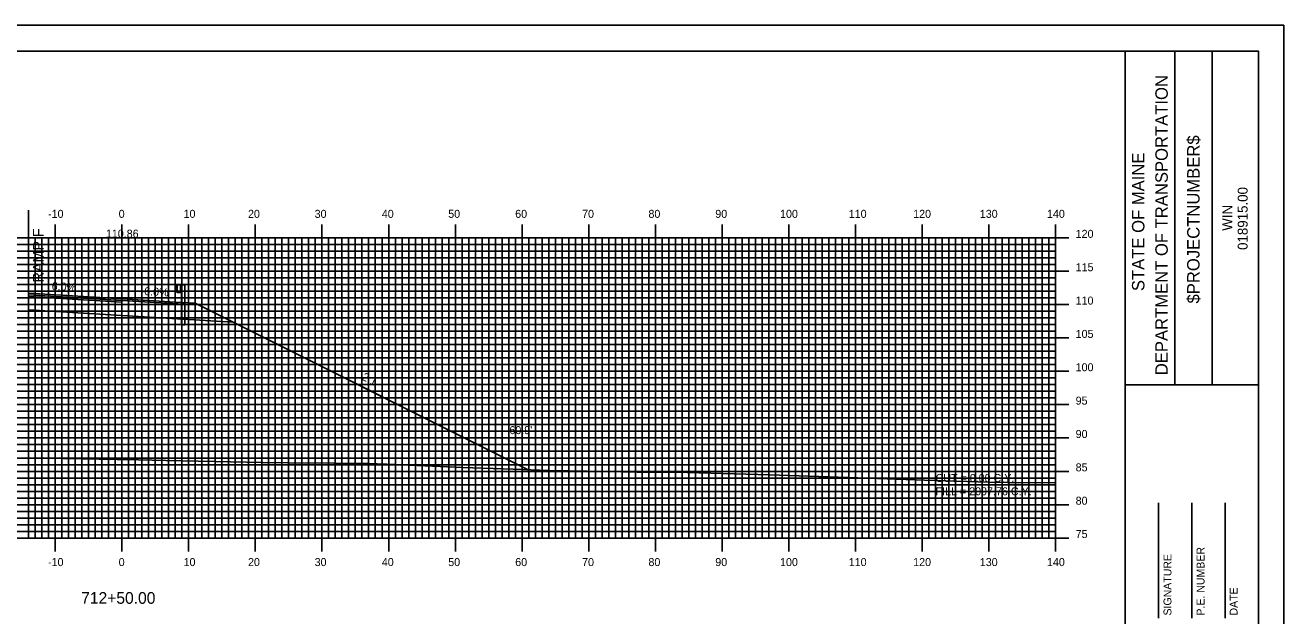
# Model space of a CAD drawing. Extents: x 855297 to 855640, y 364366 to 364586.
# Drawn here: x 855448.3 to 855637, y 364497.1 to 364585.7 of the extents above; entities that cross this region are included whole.
import ezdxf

# ---------------------------------------------------------------- set-up
doc = ezdxf.new("R2010")
doc.units = 0
for name, color, linetype in [('ANNOTATION', 7, 'Continuous'), ('BORDER', 7, 'Continuous'), ('D_Guardrail_Beam_Rt', 7, 'Continuous'), ('D_Roadway_Centerline', 7, 'Continuous'), ('D_Roadway_Centerline_Text', 7, 'Continuous'), ('D_Roadway_Edge_Shoulder', 7, 'Continuous'), ('D_Roadway_Edge_TW', 7, 'Continuous'), ('D_Roadway_Pavement', 7, 'Continuous'), ('D_Roadway_SlopeLines', 7, 'Continuous'), ('D_Roadway_SubGrade', 7, 'Continuous'), ('D_Text_Standard', 7, 'Continuous'), ('H_V ANNOTATION', 7, 'Continuous'), ('MAJOR', 7, 'Continuous'), ('MINOR', 7, 'Continuous'), ('PLOT BOUNDARY', 7, 'Continuous'), ('S_Roadway_Centerline', 7, 'Continuous')]:
    doc.layers.add(name, color=color, linetype=linetype)

msp = doc.modelspace()

# ---------------------------------------------------------------- linework, layer by layer
at = {"layer": 'BORDER'}
for p, q in [((855613.17, 364371.79), (855613.17, 364581.79)), ((855620.63, 364531.78), (855620.63, 364581.78)), ((855626.22, 364531.78), (855626.22, 364581.78)), ((855613.17, 364531.78), (855633.17, 364531.78)), ((855618.17, 364496.79), (855618.17, 364514.09)), ((855623.17, 364496.79), (855623.17, 364514.09)), ((855628.17, 364496.79), (855628.17, 364514.09))]:
    msp.add_line(p, q, dxfattribs=at)
msp.add_lwpolyline([(855313.17, 364371.79), (855633.17, 364371.79), (855633.17, 364581.79), (855313.17, 364581.79)], close=True, dxfattribs=at)
at = {"layer": 'D_Guardrail_Beam_Rt'}
for p, q in [((855470.95, 364546.64), (855470.81, 364546.54)), ((855470.81, 364546.4), (855471, 364546.26)), ((855471, 364546.06), (855470.81, 364545.93)), ((855470.81, 364545.79), (855470.95, 364545.69)), ((855471.04, 364546.66), (855470.97, 364546.65)), ((855470.97, 364545.68), (855471.04, 364545.66)), ((855471.04, 364546.75), (855471.73, 364546.75)), ((855471.04, 364545.58), (855471.04, 364546.75)), ((855471.04, 364546.2), (855471.04, 364546.13)), ((855471.73, 364545.58), (855471.04, 364545.58)), ((855471.56, 364546.75), (855471.56, 364545.58)), ((855471.67, 364546.75), (855471.67, 364545.58)), ((855471.71, 364540.75), (855471.71, 364545.58)), ((855471.73, 364546.75), (855472.2, 364546.75)), ((855471.73, 364546.75), (855471.73, 364545.58)), ((855472.2, 364546.75), (855472.2, 364540.75)), ((855471.71, 364540.75), (855472.2, 364540.75))]:
    msp.add_line(p, q, dxfattribs=at)
for centre, major_axis, start_param, end_param in [((855470.86, 364546.47), (-0.0877, 0), 5.323254, 7.243116), ((855470.86, 364545.86), (-0.0877, 0), 5.323254, 7.243116), ((855470.97, 364546.61), (-0.0417, 0), 4.907132, 5.323254), ((855470.97, 364545.72), (-0.0417, 0), 0.959931, 1.376053), ((855470.96, 364546.2), (0.0789, 0), 0, 0.959931), ((855470.96, 364546.13), (0.0789, 0), 5.323254, 6.283185)]:
    msp.add_ellipse(centre, major_axis=major_axis, ratio=0.995501, start_param=start_param, end_param=end_param, dxfattribs=at)
at = {"layer": 'D_Roadway_Centerline'}
msp.add_lwpolyline([(855448.77, 364545.48), (855462.77, 364544.64), (855470.77, 364544.16), (855473.77, 364543.98), (855479.45, 364541.14), (855523.67, 364519.03)], dxfattribs=at)
at = {"layer": 'D_Roadway_Edge_Shoulder'}
msp.add_lwpolyline([(855462.77, 364544.64), (855470.77, 364544.16), (855470.77, 364544.16), (855473.77, 364543.98), (855473.77, 364543.73), (855462.77, 364544.39)], close=True, dxfattribs=at)
at = {"layer": 'D_Roadway_Edge_TW'}
msp.add_lwpolyline([(855448.77, 364545.48), (855462.77, 364544.64), (855462.77, 364544.39), (855448.77, 364545.23)], close=True, dxfattribs=at)
at = {"layer": 'D_Roadway_Pavement'}
msp.add_lwpolyline([(855448.77, 364545.23), (855462.77, 364544.39), (855462.77, 364544.14), (855448.77, 364544.98)], close=True, dxfattribs=at)
msp.add_lwpolyline([(855462.77, 364544.39), (855462.77, 364544.14)], dxfattribs=at)
msp.add_lwpolyline([(855462.77, 364544.39), (855462.77, 364544.14)], dxfattribs=at)
at = {"layer": 'D_Roadway_SlopeLines'}
msp.add_lwpolyline([(855473.77, 364543.98), (855523.67, 364519.03)], dxfattribs=at)
at = {"layer": 'D_Roadway_SubGrade'}
msp.add_line((855448.77, 364557.94), (855448.77, 364542.98), dxfattribs=at)
for points in [[(855448.77, 364544.98), (855462.77, 364544.14), (855462.77, 364542.14), (855448.77, 364542.98)], [(855462.77, 364544.14), (855462.77, 364544.39), (855473.77, 364543.73), (855473.77, 364543.98), (855479.45, 364541.14), (855462.77, 364542.14)]]:
    msp.add_lwpolyline(points, close=True, dxfattribs=at)
at = {"layer": 'MAJOR'}
for p, q in [((855452.77, 364555.79), (855452.77, 364553.79)), ((855462.77, 364555.79), (855462.77, 364553.79)), ((855472.77, 364555.79), (855472.77, 364553.79)), ((855482.77, 364555.79), (855482.77, 364553.79)), ((855492.77, 364555.79), (855492.77, 364553.79)), ((855502.77, 364555.79), (855502.77, 364553.79)), ((855512.77, 364555.79), (855512.77, 364553.79)), ((855522.77, 364555.79), (855522.77, 364553.79)), ((855532.77, 364555.79), (855532.77, 364553.79)), ((855542.77, 364555.79), (855542.77, 364553.79)), ((855552.77, 364555.79), (855552.77, 364553.79)), ((855562.77, 364555.79), (855562.77, 364553.79)), ((855572.77, 364555.79), (855572.77, 364553.79)), ((855582.77, 364555.79), (855582.77, 364553.79)), ((855592.77, 364555.79), (855592.77, 364553.79)), ((855602.77, 364555.79), (855602.77, 364553.79)), ((855322.77, 364553.79), (855602.77, 364553.79)), ((855322.77, 364553.79), (855602.77, 364553.79)), ((855452.77, 364508.79), (855452.77, 364553.79)), ((855462.77, 364508.79), (855462.77, 364553.79)), ((855472.77, 364508.79), (855472.77, 364553.79)), ((855482.77, 364508.79), (855482.77, 364553.79)), ((855492.77, 364508.79), (855492.77, 364553.79)), ((855502.77, 364508.79), (855502.77, 364553.79)), ((855512.77, 364508.79), (855512.77, 364553.79)), ((855522.77, 364508.79), (855522.77, 364553.79)), ((855532.77, 364508.79), (855532.77, 364553.79)), ((855542.77, 364508.79), (855542.77, 364553.79)), ((855552.77, 364508.79), (855552.77, 364553.79)), ((855562.77, 364508.79), (855562.77, 364553.79)), ((855572.77, 364508.79), (855572.77, 364553.79)), ((855582.77, 364508.79), (855582.77, 364553.79)), ((855592.77, 364508.79), (855592.77, 364553.79)), ((855604.77, 364553.79), (855600.77, 364553.79)), ((855602.77, 364508.79), (855602.77, 364553.79)), ((855602.77, 364508.79), (855602.77, 364553.79)), ((855322.77, 364548.79), (855602.77, 364548.79)), ((855604.77, 364548.79), (855600.77, 364548.79)), ((855322.77, 364543.79), (855602.77, 364543.79)), ((855604.77, 364543.79), (855600.77, 364543.79)), ((855322.77, 364538.79), (855602.77, 364538.79)), ((855604.77, 364538.79), (855600.77, 364538.79)), ((855322.77, 364533.79), (855602.77, 364533.79)), ((855604.77, 364533.79), (855600.77, 364533.79)), ((855322.77, 364528.79), (855602.77, 364528.79)), ((855604.77, 364528.79), (855600.77, 364528.79)), ((855322.77, 364523.79), (855602.77, 364523.79)), ((855604.77, 364523.79), (855600.77, 364523.79)), ((855322.77, 364518.79), (855602.77, 364518.79)), ((855604.77, 364518.79), (855600.77, 364518.79)), ((855322.77, 364513.79), (855602.77, 364513.79)), ((855604.77, 364513.79), (855600.77, 364513.79)), ((855322.77, 364508.79), (855602.77, 364508.79)), ((855322.77, 364508.79), (855602.77, 364508.79)), ((855452.77, 364506.78), (855452.77, 364508.79)), ((855462.77, 364506.78), (855462.77, 364508.79)), ((855472.77, 364506.78), (855472.77, 364508.79)), ((855482.77, 364506.78), (855482.77, 364508.79)), ((855492.77, 364506.78), (855492.77, 364508.79)), ((855502.77, 364506.78), (855502.77, 364508.79)), ((855512.77, 364506.78), (855512.77, 364508.79)), ((855522.77, 364506.78), (855522.77, 364508.79)), ((855532.77, 364506.78), (855532.77, 364508.79)), ((855542.77, 364506.78), (855542.77, 364508.79)), ((855552.77, 364506.78), (855552.77, 364508.79)), ((855562.77, 364506.78), (855562.77, 364508.79)), ((855572.77, 364506.78), (855572.77, 364508.79)), ((855582.77, 364506.78), (855582.77, 364508.79)), ((855592.77, 364506.78), (855592.77, 364508.79)), ((855604.77, 364508.79), (855600.77, 364508.79)), ((855602.77, 364506.78), (855602.77, 364508.79))]:
    msp.add_line(p, q, dxfattribs=at)
at = {"layer": 'MINOR'}
for p, q in [((855322.77, 364552.79), (855602.77, 364552.79)), ((855448.77, 364508.79), (855448.77, 364553.79)), ((855449.77, 364508.79), (855449.77, 364553.79)), ((855450.77, 364508.79), (855450.77, 364553.79)), ((855451.77, 364508.79), (855451.77, 364553.79)), ((855453.77, 364508.79), (855453.77, 364553.79)), ((855454.77, 364508.79), (855454.77, 364553.79)), ((855455.77, 364508.79), (855455.77, 364553.79)), ((855456.77, 364508.79), (855456.77, 364553.79)), ((855457.77, 364508.79), (855457.77, 364553.79)), ((855458.77, 364508.79), (855458.77, 364553.79)), ((855459.77, 364508.79), (855459.77, 364553.79)), ((855460.77, 364508.79), (855460.77, 364553.79)), ((855461.77, 364508.79), (855461.77, 364553.79)), ((855463.77, 364508.79), (855463.77, 364553.79)), ((855464.77, 364508.79), (855464.77, 364553.79)), ((855465.77, 364508.79), (855465.77, 364553.79)), ((855466.77, 364508.79), (855466.77, 364553.79)), ((855467.77, 364508.79), (855467.77, 364553.79)), ((855468.77, 364508.79), (855468.77, 364553.79)), ((855469.77, 364508.79), (855469.77, 364553.79)), ((855470.77, 364508.79), (855470.77, 364553.79)), ((855471.77, 364508.79), (855471.77, 364553.79)), ((855473.77, 364508.79), (855473.77, 364553.79)), ((855474.77, 364508.79), (855474.77, 364553.79)), ((855475.77, 364508.79), (855475.77, 364553.79)), ((855476.77, 364508.79), (855476.77, 364553.79)), ((855477.77, 364508.79), (855477.77, 364553.79)), ((855478.77, 364508.79), (855478.77, 364553.79)), ((855479.77, 364508.79), (855479.77, 364553.79)), ((855480.77, 364508.79), (855480.77, 364553.79)), ((855481.77, 364508.79), (855481.77, 364553.79)), ((855483.77, 364508.79), (855483.77, 364553.79)), ((855484.77, 364508.79), (855484.77, 364553.79)), ((855485.77, 364508.79), (855485.77, 364553.79)), ((855486.77, 364508.79), (855486.77, 364553.79)), ((855487.77, 364508.79), (855487.77, 364553.79)), ((855488.77, 364508.79), (855488.77, 364553.79)), ((855489.77, 364508.79), (855489.77, 364553.79)), ((855490.77, 364508.79), (855490.77, 364553.79)), ((855491.77, 364508.79), (855491.77, 364553.79)), ((855493.77, 364508.79), (855493.77, 364553.79)), ((855494.77, 364508.79), (855494.77, 364553.79)), ((855495.77, 364508.79), (855495.77, 364553.79)), ((855496.77, 364508.79), (855496.77, 364553.79)), ((855497.77, 364508.79), (855497.77, 364553.79)), ((855498.77, 364508.79), (855498.77, 364553.79)), ((855499.77, 364508.79), (855499.77, 364553.79)), ((855500.77, 364508.79), (855500.77, 364553.79)), ((855501.77, 364508.79), (855501.77, 364553.79)), ((855503.77, 364508.79), (855503.77, 364553.79)), ((855504.77, 364508.79), (855504.77, 364553.79)), ((855505.77, 364508.79), (855505.77, 364553.79)), ((855506.77, 364508.79), (855506.77, 364553.79)), ((855507.77, 364508.79), (855507.77, 364553.79)), ((855508.77, 364508.79), (855508.77, 364553.79)), ((855509.77, 364508.79), (855509.77, 364553.79)), ((855510.77, 364508.79), (855510.77, 364553.79)), ((855511.77, 364508.79), (855511.77, 364553.79)), ((855513.77, 364508.79), (855513.77, 364553.79)), ((855514.77, 364508.79), (855514.77, 364553.79)), ((855515.77, 364508.79), (855515.77, 364553.79)), ((855516.77, 364508.79), (855516.77, 364553.79)), ((855517.77, 364508.79), (855517.77, 364553.79)), ((855518.77, 364508.79), (855518.77, 364553.79)), ((855519.77, 364508.79), (855519.77, 364553.79)), ((855520.77, 364508.79), (855520.77, 364553.79)), ((855521.77, 364508.79), (855521.77, 364553.79)), ((855523.77, 364508.79), (855523.77, 364553.79)), ((855524.77, 364508.79), (855524.77, 364553.79)), ((855525.77, 364508.79), (855525.77, 364553.79)), ((855526.77, 364508.79), (855526.77, 364553.79)), ((855527.77, 364508.79), (855527.77, 364553.79)), ((855528.77, 364508.79), (855528.77, 364553.79)), ((855529.77, 364508.79), (855529.77, 364553.79)), ((855530.77, 364508.79), (855530.77, 364553.79)), ((855531.77, 364508.79), (855531.77, 364553.79)), ((855533.77, 364508.79), (855533.77, 364553.79)), ((855534.77, 364508.79), (855534.77, 364553.79)), ((855535.77, 364508.79), (855535.77, 364553.79)), ((855536.77, 364508.79), (855536.77, 364553.79)), ((855537.77, 364508.79), (855537.77, 364553.79)), ((855538.77, 364508.79), (855538.77, 364553.79)), ((855539.77, 364508.79), (855539.77, 364553.79)), ((855540.77, 364508.79), (855540.77, 364553.79)), ((855541.77, 364508.79), (855541.77, 364553.79)), ((855543.77, 364508.79), (855543.77, 364553.79)), ((855544.77, 364508.79), (855544.77, 364553.79)), ((855545.77, 364508.79), (855545.77, 364553.79)), ((855546.77, 364508.79), (855546.77, 364553.79)), ((855547.77, 364508.79), (855547.77, 364553.79)), ((855548.77, 364508.79), (855548.77, 364553.79)), ((855549.77, 364508.79), (855549.77, 364553.79)), ((855550.77, 364508.79), (855550.77, 364553.79)), ((855551.77, 364508.79), (855551.77, 364553.79)), ((855553.77, 364508.79), (855553.77, 364553.79)), ((855554.77, 364508.79), (855554.77, 364553.79)), ((855555.77, 364508.79), (855555.77, 364553.79)), ((855556.77, 364508.79), (855556.77, 364553.79)), ((855557.77, 364508.79), (855557.77, 364553.79)), ((855558.77, 364508.79), (855558.77, 364553.79)), ((855559.77, 364508.79), (855559.77, 364553.79)), ((855560.77, 364508.79), (855560.77, 364553.79)), ((855561.77, 364508.79), (855561.77, 364553.79)), ((855563.77, 364508.79), (855563.77, 364553.79)), ((855564.77, 364508.79), (855564.77, 364553.79)), ((855565.77, 364508.79), (855565.77, 364553.79)), ((855566.77, 364508.79), (855566.77, 364553.79)), ((855567.77, 364508.79), (855567.77, 364553.79)), ((855568.77, 364508.79), (855568.77, 364553.79)), ((855569.77, 364508.79), (855569.77, 364553.79)), ((855570.77, 364508.79), (855570.77, 364553.79)), ((855571.77, 364508.79), (855571.77, 364553.79)), ((855573.77, 364508.79), (855573.77, 364553.79)), ((855574.77, 364508.79), (855574.77, 364553.79)), ((855575.77, 364508.79), (855575.77, 364553.79)), ((855576.77, 364508.79), (855576.77, 364553.79)), ((855577.77, 364508.79), (855577.77, 364553.79)), ((855578.77, 364508.79), (855578.77, 364553.79)), ((855579.77, 364508.79), (855579.77, 364553.79)), ((855580.77, 364508.79), (855580.77, 364553.79)), ((855581.77, 364508.79), (855581.77, 364553.79)), ((855583.77, 364508.79), (855583.77, 364553.79)), ((855584.77, 364508.79), (855584.77, 364553.79)), ((855585.77, 364508.79), (855585.77, 364553.79)), ((855586.77, 364508.79), (855586.77, 364553.79)), ((855587.77, 364508.79), (855587.77, 364553.79)), ((855588.77, 364508.79), (855588.77, 364553.79)), ((855589.77, 364508.79), (855589.77, 364553.79)), ((855590.77, 364508.79), (855590.77, 364553.79)), ((855591.77, 364508.79), (855591.77, 364553.79)), ((855593.77, 364508.79), (855593.77, 364553.79)), ((855594.77, 364508.79), (855594.77, 364553.79)), ((855595.77, 364508.79), (855595.77, 364553.79)), ((855596.77, 364508.79), (855596.77, 364553.79)), ((855597.77, 364508.79), (855597.77, 364553.79)), ((855598.77, 364508.79), (855598.77, 364553.79)), ((855599.77, 364508.79), (855599.77, 364553.79)), ((855600.77, 364508.79), (855600.77, 364553.79)), ((855602.77, 364552.79), (855600.77, 364552.79)), ((855601.77, 364508.79), (855601.77, 364553.79)), ((855322.77, 364551.79), (855602.77, 364551.79)), ((855322.77, 364550.79), (855602.77, 364550.79)), ((855602.77, 364551.79), (855600.77, 364551.79)), ((855602.77, 364550.79), (855600.77, 364550.79)), ((855322.77, 364549.79), (855602.77, 364549.79)), ((855602.77, 364549.79), (855600.77, 364549.79)), ((855322.77, 364547.79), (855602.77, 364547.79)), ((855602.77, 364547.79), (855600.77, 364547.79)), ((855322.77, 364546.79), (855602.77, 364546.79)), ((855322.77, 364545.79), (855602.77, 364545.79)), ((855602.77, 364546.79), (855600.77, 364546.79)), ((855602.77, 364545.79), (855600.77, 364545.79)), ((855322.77, 364544.79), (855602.77, 364544.79)), ((855602.77, 364544.79), (855600.77, 364544.79)), ((855322.77, 364542.79), (855602.77, 364542.79)), ((855322.77, 364541.79), (855602.77, 364541.79)), ((855602.77, 364542.79), (855600.77, 364542.79)), ((855602.77, 364541.79), (855600.77, 364541.79)), ((855322.77, 364540.79), (855602.77, 364540.79)), ((855322.77, 364539.79), (855602.77, 364539.79)), ((855602.77, 364540.79), (855600.77, 364540.79)), ((855602.77, 364539.79), (855600.77, 364539.79)), ((855322.77, 364537.79), (855602.77, 364537.79)), ((855602.77, 364537.79), (855600.77, 364537.79)), ((855322.77, 364536.79), (855602.77, 364536.79)), ((855322.77, 364535.79), (855602.77, 364535.79)), ((855602.77, 364536.79), (855600.77, 364536.79)), ((855602.77, 364535.79), (855600.77, 364535.79)), ((855322.77, 364534.79), (855602.77, 364534.79)), ((855602.77, 364534.79), (855600.77, 364534.79)), ((855322.77, 364532.79), (855602.77, 364532.79)), ((855602.77, 364532.79), (855600.77, 364532.79)), ((855322.77, 364531.79), (855602.77, 364531.79)), ((855322.77, 364530.79), (855602.77, 364530.79)), ((855602.77, 364531.79), (855600.77, 364531.79)), ((855602.77, 364530.79), (855600.77, 364530.79)), ((855322.77, 364529.79), (855602.77, 364529.79)), ((855602.77, 364529.79), (855600.77, 364529.79)), ((855322.77, 364527.79), (855602.77, 364527.79)), ((855322.77, 364526.79), (855602.77, 364526.79)), ((855602.77, 364527.79), (855600.77, 364527.79)), ((855602.77, 364526.79), (855600.77, 364526.79)), ((855322.77, 364525.79), (855602.77, 364525.79)), ((855322.77, 364524.79), (855602.77, 364524.79)), ((855602.77, 364525.79), (855600.77, 364525.79)), ((855602.77, 364524.79), (855600.77, 364524.79)), ((855322.77, 364522.79), (855602.77, 364522.79)), ((855602.77, 364522.79), (855600.77, 364522.79)), ((855322.77, 364521.79), (855602.77, 364521.79)), ((855322.77, 364520.79), (855602.77, 364520.79)), ((855602.77, 364521.79), (855600.77, 364521.79)), ((855602.77, 364520.79), (855600.77, 364520.79)), ((855322.77, 364519.79), (855602.77, 364519.79)), ((855602.77, 364519.79), (855600.77, 364519.79)), ((855322.77, 364517.79), (855602.77, 364517.79)), ((855322.77, 364516.79), (855602.77, 364516.79)), ((855602.77, 364517.79), (855600.77, 364517.79)), ((855602.77, 364516.79), (855600.77, 364516.79)), ((855322.77, 364515.79), (855602.77, 364515.79)), ((855602.77, 364515.79), (855600.77, 364515.79)), ((855322.77, 364514.79), (855602.77, 364514.79)), ((855602.77, 364514.79), (855600.77, 364514.79)), ((855322.77, 364512.79), (855602.77, 364512.79)), ((855322.77, 364511.79), (855602.77, 364511.79)), ((855602.77, 364512.79), (855600.77, 364512.79)), ((855602.77, 364511.79), (855600.77, 364511.79)), ((855322.77, 364510.79), (855602.77, 364510.79)), ((855322.77, 364509.79), (855602.77, 364509.79)), ((855602.77, 364510.79), (855600.77, 364510.79)), ((855602.77, 364509.79), (855600.77, 364509.79))]:
    msp.add_line(p, q, dxfattribs=at)
at = {"layer": 'PLOT BOUNDARY'}
msp.add_lwpolyline([(855296.98, 364365.67), (855636.98, 364365.67), (855636.98, 364585.67), (855296.98, 364585.67)], close=True, dxfattribs=at)
at = {"layer": 'S_Roadway_Centerline'}
msp.add_lwpolyline([(855445.9, 364520.79), (855451.26, 364520.75), (855462.05, 364520.59), (855464.12, 364520.55), (855465.26, 364520.54), (855469.36, 364520.44), (855483.88, 364520.12), (855487.69, 364520.07), (855494.57, 364520.03), (855499.64, 364519.98), (855502.47, 364519.89), (855513.91, 364519.39), (855521.44, 364519.12), (855526.72, 364518.92), (855535.43, 364518.77), (855540.02, 364518.67), (855547.5, 364518.64), (855559.87, 364518.28), (855559.89, 364518.28), (855559.91, 364518.28), (855577.52, 364517.68), (855583.11, 364517.46), (855592.71, 364517.18), (855595.56, 364517.13), (855597.18, 364517.08), (855602.77, 364517.14)], dxfattribs=at)

# ---------------------------------------------------------------- texts
at = {"layer": 'ANNOTATION'}
for s, height, rotation, p in [('RAMP F', 1.6, 90, (855451.03, 364547.12)), ('6.0%', 1.2, 356.5664, (855452.22, 364545.99)), ('-6.0%', 1.2, 356.5664, (855465.55, 364545.25)), ('2:1', 1.2, 333.4349, (855498.65, 364532.58))]:
    msp.add_text(s, height=height, rotation=rotation, dxfattribs=at).set_placement(p)
at = {"layer": 'BORDER'}
for s, height, p in [('DEPARTMENT OF TRANSPORTATION', 1.8635, (855619.58, 364533.2)), ('$PROJECTNUMBER$', 1.8635, (855624.35, 364543.95)), ('STATE OF MAINE', 1.8635, (855616.08, 364545.81)), ('018915.00', 1.491, (855631.56, 364551.98)), ('WIN', 1.491, (855629.24, 364554.85)), ('P.E. NUMBER', 1.1811, (855625.09, 364497.18)), ('SIGNATURE', 1.181, (855620.13, 364497.18)), ('DATE', 1.181, (855630.05, 364497.18))]:
    msp.add_text(s, height=height, rotation=90, dxfattribs=at).set_placement(p)
at = {"layer": 'D_Roadway_Centerline_Text'}
msp.add_text('110.86', height=1.2, dxfattribs=at).set_placement((855460.37, 364553.82))
at = {"layer": 'D_Text_Standard'}
for s, p in [("60.9'", (855520.87, 364524.37)), ('CUT = 0.00 C.Y.', (855584.77, 364517.19)), ('FILL = 2097.76 C.Y.', (855584.77, 364515.2))]:
    msp.add_text(s, height=1.2, dxfattribs=at).set_placement(p)
at = {"layer": 'H_V ANNOTATION'}
for s, height, p in [('-10', 1.2, (855451.7, 364556.79)), ('0', 1.2, (855462.29, 364556.79)), ('10', 1.2, (855472.02, 364556.79)), ('20', 1.2, (855481.68, 364556.79)), ('30', 1.2, (855491.67, 364556.79)), ('40', 1.2, (855501.74, 364556.79)), ('50', 1.2, (855511.7, 364556.79)), ('60', 1.2, (855521.74, 364556.79)), ('70', 1.2, (855531.77, 364556.79)), ('80', 1.2, (855541.72, 364556.79)), ('90', 1.2, (855551.74, 364556.79)), ('100', 1.2, (855561.45, 364556.79)), ('110', 1.2, (855571.75, 364556.79)), ('120', 1.2, (855581.41, 364556.79)), ('130', 1.2, (855591.4, 364556.79)), ('140', 1.2, (855601.47, 364556.79)), ('120', 1.2, (855605.77, 364553.79)), ('115', 1.2, (855605.77, 364548.79)), ('110', 1.2, (855605.77, 364543.79)), ('105', 1.2, (855605.77, 364538.79)), ('100', 1.2, (855605.77, 364533.79)), ('95', 1.2, (855605.77, 364528.79)), ('90', 1.2, (855605.77, 364523.79)), ('85', 1.2, (855605.77, 364518.79)), ('80', 1.2, (855605.77, 364513.79)), ('75', 1.2, (855605.77, 364508.79)), ('-10', 1.2, (855451.7, 364504.59)), ('0', 1.2, (855462.29, 364504.59)), ('10', 1.2, (855472.02, 364504.59)), ('20', 1.2, (855481.68, 364504.59)), ('30', 1.2, (855491.67, 364504.59)), ('40', 1.2, (855501.74, 364504.59)), ('50', 1.2, (855511.7, 364504.59)), ('60', 1.2, (855521.74, 364504.59)), ('70', 1.2, (855531.77, 364504.59)), ('80', 1.2, (855541.72, 364504.59)), ('90', 1.2, (855551.74, 364504.59)), ('100', 1.2, (855561.45, 364504.59)), ('110', 1.2, (855571.75, 364504.59)), ('120', 1.2, (855581.41, 364504.59)), ('130', 1.2, (855591.4, 364504.59)), ('140', 1.2, (855601.47, 364504.59)), ('712+50.00', 1.75, (855456.67, 364498.94))]:
    msp.add_text(s, height=height, dxfattribs=at).set_placement(p)

doc.saveas('drawing.dxf')
